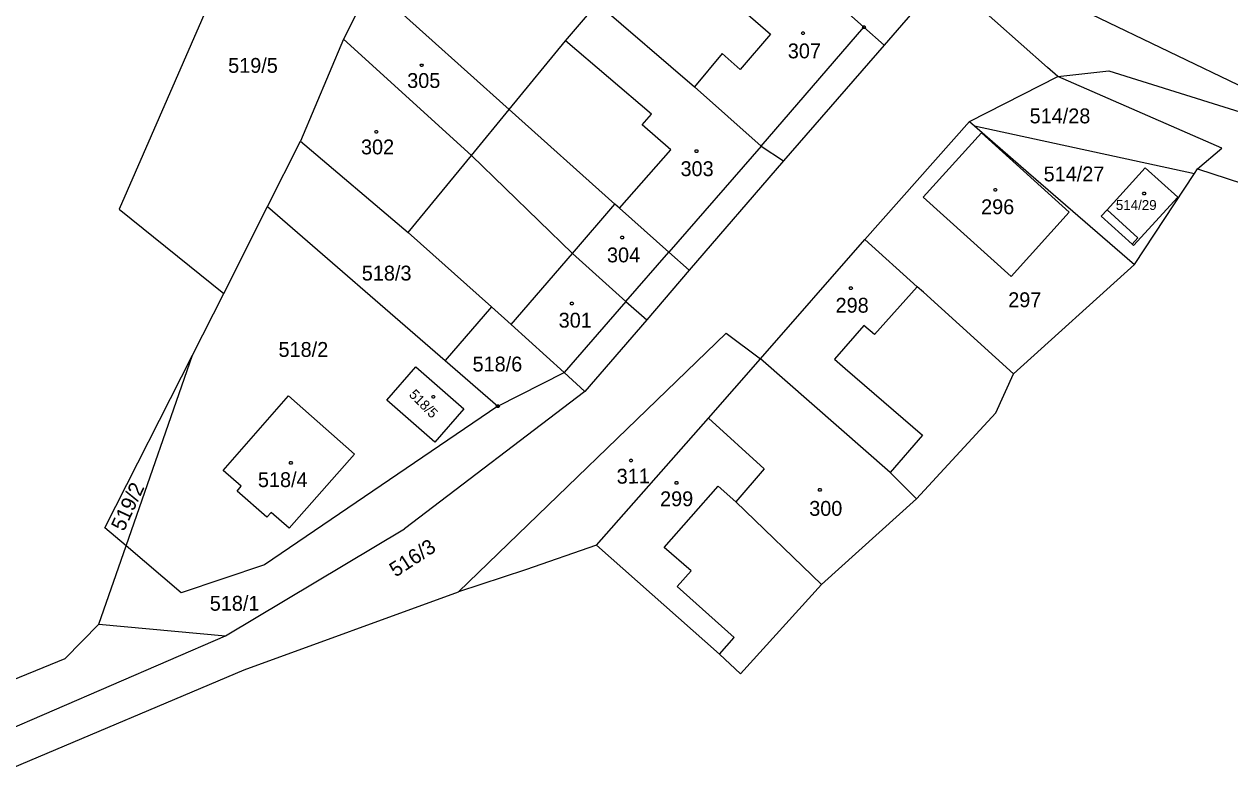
# Model space of a CAD drawing. Extents: x -634640 to -629202, y -1196156 to -1190068.
# Drawn here: x -631922.1 to -631784.1, y -1192813.3 to -1192727.8 of the extents above; entities that cross this region are included whole.
import ezdxf

# ---------------------------------------------------------------- set-up
doc = ezdxf.new("R2010")
doc.units = 0
for name, color, linetype in [('Vrstva 1', 7, 'Continuous'), ('Vrstva 2', 7, 'Continuous'), ('Vrstva 3', 7, 'Continuous'), ('Vrstva 4', 7, 'Continuous'), ('Vrstva 5', 7, 'Continuous'), ('Vrstva 8', 7, 'Continuous')]:
    doc.layers.add(name, color=color, linetype=linetype)

msp = doc.modelspace()

# ---------------------------------------------------------------- linework, layer by layer
at = {"layer": 'Vrstva 1'}
for p, q in [((-631845.21, -1192711.13), (-631825.94, -1192728.19)), ((-631816.78, -1192722.29), (-631823.63, -1192730.27)), ((-631882.43, -1192723.39), (-631885.53, -1192729.56)), ((-631882.43, -1192723.39), (-631866.57, -1192737.61)), ((-631860.1, -1192729.75), (-631856.45, -1192725.49)), ((-631856.45, -1192725.49), (-631845.36, -1192735.03)), ((-631804.93, -1192732.81), (-631814.33, -1192724.46)), ((-631782.1, -1192735.29), (-631799.89, -1192726.74)), ((-631825.94, -1192728.19), (-631823.63, -1192730.27)), ((-631885.53, -1192729.56), (-631890.46, -1192741.24)), ((-631885.53, -1192729.56), (-631870.89, -1192742.87)), ((-631866.57, -1192737.61), (-631860.1, -1192729.75)), ((-631823.63, -1192730.27), (-631835.15, -1192743.51)), ((-631813.87, -1192738.98), (-631803.76, -1192733.85)), ((-631803.76, -1192733.85), (-631804.93, -1192732.81)), ((-631803.76, -1192733.85), (-631797.91, -1192733.18)), ((-631784.98, -1192742.05), (-631803.76, -1192733.85)), ((-631797.91, -1192733.18), (-631759.33, -1192745.33)), ((-631845.36, -1192735.03), (-631837.71, -1192741.81)), ((-631870.89, -1192742.87), (-631866.57, -1192737.61)), ((-631854.45, -1192748.46), (-631866.57, -1192737.61)), ((-631825.83, -1192752.5), (-631813.87, -1192738.98)), ((-631813.87, -1192738.98), (-631813.29, -1192739.49)), ((-631813.29, -1192739.49), (-631807.11, -1192744.88)), ((-631813.29, -1192739.49), (-631788.11, -1192744.93)), ((-631819.15, -1192747.64), (-631812.48, -1192740.28)), ((-631812.48, -1192740.28), (-631802.46, -1192749.37)), ((-631894.22, -1192748.71), (-631890.46, -1192741.24)), ((-631890.46, -1192741.24), (-631878.11, -1192751.71)), ((-631837.71, -1192741.81), (-631835.15, -1192743.51)), ((-631787.77, -1192744.42), (-631784.98, -1192742.05)), ((-631878.11, -1192751.71), (-631870.89, -1192742.87)), ((-631870.89, -1192742.87), (-631859.32, -1192754.09)), ((-631835.15, -1192743.51), (-631845.94, -1192756.02)), ((-631807.11, -1192744.88), (-631794.96, -1192755.34)), ((-631794.96, -1192755.34), (-631788.11, -1192744.93)), ((-631788.11, -1192744.93), (-631787.77, -1192744.42)), ((-631787.77, -1192744.42), (-631778.3, -1192747.47)), ((-631809.1, -1192756.72), (-631819.15, -1192747.64)), ((-631899.23, -1192758.66), (-631894.22, -1192748.71)), ((-631894.22, -1192748.71), (-631873.88, -1192766.35)), ((-631853.91, -1192748.89), (-631854.45, -1192748.46)), ((-631848.27, -1192753.93), (-631853.91, -1192748.89)), ((-631802.46, -1192749.37), (-631809.1, -1192756.72)), ((-631878.11, -1192751.71), (-631868.6, -1192760.2)), ((-631837.78, -1192766.16), (-631825.83, -1192752.5)), ((-631819.85, -1192757.92), (-631825.83, -1192752.5)), ((-631859.32, -1192754.09), (-631853.2, -1192759.59)), ((-631845.94, -1192756.02), (-631848.27, -1192753.93)), ((-631845.94, -1192756.02), (-631850.81, -1192761.67)), ((-631808.82, -1192767.85), (-631794.96, -1192755.34)), ((-631902.8, -1192765.75), (-631899.23, -1192758.66)), ((-631819.13, -1192758.51), (-631819.85, -1192757.92)), ((-631808.82, -1192767.85), (-631819.13, -1192758.51)), ((-631868.6, -1192760.2), (-631873.88, -1192766.35)), ((-631868.6, -1192760.2), (-631866.34, -1192762.21)), ((-631853.2, -1192759.59), (-631850.81, -1192761.67)), ((-631850.81, -1192761.67), (-631857.9, -1192769.89)), ((-631866.34, -1192762.21), (-631860.28, -1192767.72)), ((-631872.35, -1192792.8), (-631841.7, -1192763.22)), ((-631841.7, -1192763.22), (-631837.78, -1192766.16)), ((-631912.85, -1192785.48), (-631902.8, -1192765.75)), ((-631910.42, -1192787.55), (-631902.8, -1192765.75)), ((-631873.88, -1192766.35), (-631867.85, -1192771.57)), ((-631843.74, -1192772.96), (-631837.78, -1192766.16)), ((-631822.95, -1192779.17), (-631837.78, -1192766.16)), ((-631867.85, -1192771.57), (-631860.28, -1192767.72)), ((-631860.28, -1192767.72), (-631857.9, -1192769.89)), ((-631810.86, -1192772.33), (-631808.82, -1192767.85)), ((-631857.9, -1192769.89), (-631878.54, -1192785.62)), ((-631867.85, -1192771.57), (-631894.58, -1192789.74)), ((-631819.94, -1192782.17), (-631810.86, -1192772.33)), ((-631856.56, -1192787.49), (-631843.74, -1192772.96)), ((-631843.74, -1192772.96), (-631837.35, -1192778.76)), ((-631837.35, -1192778.76), (-631840.63, -1192782.51)), ((-631819.94, -1192782.17), (-631822.95, -1192779.17)), ((-631819.94, -1192782.17), (-631830.81, -1192791.99)), ((-631840.63, -1192782.51), (-631830.81, -1192791.99)), ((-631910.42, -1192787.55), (-631912.85, -1192785.48)), ((-631899.04, -1192797.87), (-631878.54, -1192785.62)), ((-631913.55, -1192796.51), (-631910.42, -1192787.55)), ((-631904.09, -1192792.92), (-631910.42, -1192787.55)), ((-631856.56, -1192787.49), (-631864.7, -1192790.29)), ((-631842.5, -1192799.96), (-631856.56, -1192787.49)), ((-631894.58, -1192789.74), (-631904.09, -1192792.92)), ((-631864.7, -1192790.29), (-631872.35, -1192792.8)), ((-631830.81, -1192791.99), (-631840.07, -1192802.22)), ((-631896.9, -1192801.74), (-631872.35, -1192792.8)), ((-631917.39, -1192800.45), (-631913.55, -1192796.51)), ((-631913.55, -1192796.51), (-631899.04, -1192797.87)), ((-631925.18, -1192809.17), (-631899.04, -1192797.87)), ((-631840.07, -1192802.22), (-631842.5, -1192799.96)), ((-631956.23, -1192816.21), (-631917.39, -1192800.45)), ((-631923.43, -1192812.98), (-631896.9, -1192801.74))]:
    msp.add_line(p, q, dxfattribs=at)
for points in [[(-631893.53, -1192708.5), (-631911.2, -1192749.01), (-631899.23, -1192758.66)], [(-631790.03, -1192747.65), (-631793.74, -1192744.29), (-631798.11, -1192749.1)], [(-631795.26, -1192753.03), (-631795.07, -1192753.2), (-631790.03, -1192747.65)], [(-631798.11, -1192749.1), (-631798.79, -1192749.84), (-631795.26, -1192753.03)], [(-631880.58, -1192770.88), (-631877.25, -1192767.07), (-631871.73, -1192771.88), (-631875.07, -1192775.68), (-631880.58, -1192770.88)], [(-631891.74, -1192785.54), (-631893.82, -1192783.72), (-631894.31, -1192784.29), (-631897.71, -1192781.31), (-631897.22, -1192780.74), (-631899.3, -1192778.92), (-631891.81, -1192770.38), (-631884.26, -1192777.06), (-631891.74, -1192785.54)]]:
    msp.add_lwpolyline(points, dxfattribs=at)
at = {"layer": 'Vrstva 3'}
for points in [[(-631876.49, -1192732.41), (-631876.4, -1192732.56), (-631876.49, -1192732.71), (-631876.67, -1192732.71), (-631876.76, -1192732.56), (-631876.67, -1192732.41), (-631876.49, -1192732.41)], [(-631881.68, -1192740.03), (-631881.59, -1192740.18), (-631881.68, -1192740.33), (-631881.86, -1192740.33), (-631881.95, -1192740.18), (-631881.86, -1192740.03), (-631881.68, -1192740.03)], [(-631852.52, -1192777.63), (-631852.43, -1192777.78), (-631852.52, -1192777.93), (-631852.7, -1192777.93), (-631852.79, -1192777.78), (-631852.7, -1192777.63), (-631852.52, -1192777.63)], [(-631830.91, -1192780.99), (-631830.82, -1192781.14), (-631830.91, -1192781.29), (-631831.09, -1192781.29), (-631831.18, -1192781.14), (-631831.09, -1192780.99), (-631830.91, -1192780.99)]]:
    msp.add_lwpolyline(points, dxfattribs=at)
at = {"layer": 'Vrstva 4'}
for p, q in [((-631843.6, -1192722.93), (-631836.65, -1192729.01)), ((-631837.71, -1192741.81), (-631825.94, -1192728.19)), ((-631850.26, -1192738.14), (-631860.1, -1192729.75)), ((-631836.65, -1192729.01), (-631840.1, -1192733.04)), ((-631842.16, -1192731.21), (-631845.36, -1192735.03)), ((-631840.1, -1192733.04), (-631842.16, -1192731.21)), ((-631851.33, -1192739.37), (-631850.26, -1192738.14)), ((-631848.07, -1192742.22), (-631851.33, -1192739.37)), ((-631853.91, -1192748.89), (-631848.07, -1192742.22)), ((-631837.71, -1192741.81), (-631848.27, -1192753.93)), ((-631859.32, -1192754.09), (-631854.45, -1192748.46)), ((-631866.34, -1192762.21), (-631859.32, -1192754.09)), ((-631853.2, -1192759.59), (-631848.27, -1192753.93)), ((-631819.85, -1192757.92), (-631824.72, -1192763.35)), ((-631853.2, -1192759.59), (-631860.28, -1192767.72)), ((-631825.94, -1192762.33), (-631829.3, -1192766.18)), ((-631824.72, -1192763.35), (-631825.94, -1192762.33)), ((-631829.3, -1192766.18), (-631828.09, -1192767.24)), ((-631828.09, -1192767.24), (-631819.25, -1192774.89)), ((-631819.25, -1192774.89), (-631822.95, -1192779.17)), ((-631848.81, -1192787.73), (-631842.64, -1192780.73)), ((-631842.64, -1192780.73), (-631840.63, -1192782.51)), ((-631845.73, -1192790.43), (-631848.81, -1192787.73)), ((-631847.34, -1192792.2), (-631845.73, -1192790.43)), ((-631840.79, -1192798.04), (-631847.34, -1192792.2)), ((-631842.5, -1192799.96), (-631840.79, -1192798.04))]:
    msp.add_line(p, q, dxfattribs=at)
msp.add_lwpolyline([(-631798.11, -1192749.1), (-631794.58, -1192752.29), (-631795.26, -1192753.03)], dxfattribs=at)
at = {"layer": 'Vrstva 5'}
for points in [[(-631832.84, -1192728.73), (-631832.75, -1192728.88), (-631832.84, -1192729.03), (-631833.02, -1192729.03), (-631833.11, -1192728.88), (-631833.02, -1192728.73), (-631832.84, -1192728.73)], [(-631845.02, -1192742.25), (-631844.93, -1192742.4), (-631845.02, -1192742.55), (-631845.2, -1192742.55), (-631845.29, -1192742.4), (-631845.2, -1192742.25), (-631845.02, -1192742.25)], [(-631810.81, -1192746.67), (-631810.72, -1192746.82), (-631810.81, -1192746.97), (-631810.99, -1192746.97), (-631811.08, -1192746.82), (-631810.99, -1192746.67), (-631810.81, -1192746.67)], [(-631793.78, -1192747.09), (-631793.69, -1192747.24), (-631793.78, -1192747.39), (-631793.96, -1192747.39), (-631794.05, -1192747.24), (-631793.96, -1192747.09), (-631793.78, -1192747.09)], [(-631853.54, -1192752.13), (-631853.45, -1192752.28), (-631853.54, -1192752.43), (-631853.72, -1192752.43), (-631853.81, -1192752.28), (-631853.72, -1192752.13), (-631853.54, -1192752.13)], [(-631827.35, -1192757.93), (-631827.26, -1192758.08), (-631827.35, -1192758.23), (-631827.53, -1192758.23), (-631827.62, -1192758.08), (-631827.53, -1192757.93), (-631827.35, -1192757.93)], [(-631859.29, -1192759.68), (-631859.2, -1192759.83), (-631859.29, -1192759.98), (-631859.47, -1192759.98), (-631859.56, -1192759.83), (-631859.47, -1192759.68), (-631859.29, -1192759.68)], [(-631875.15, -1192770.35), (-631875.06, -1192770.5), (-631875.15, -1192770.65), (-631875.33, -1192770.65), (-631875.42, -1192770.5), (-631875.33, -1192770.35), (-631875.15, -1192770.35)], [(-631891.46, -1192777.92), (-631891.37, -1192778.07), (-631891.46, -1192778.22), (-631891.64, -1192778.22), (-631891.73, -1192778.07), (-631891.64, -1192777.92), (-631891.46, -1192777.92)], [(-631847.31, -1192780.18), (-631847.22, -1192780.33), (-631847.31, -1192780.48), (-631847.49, -1192780.48), (-631847.58, -1192780.33), (-631847.49, -1192780.18), (-631847.31, -1192780.18)]]:
    msp.add_lwpolyline(points, dxfattribs=at)
at = {"layer": 'Vrstva 8'}
for points in [[(-631825.85, -1192728.04), (-631825.76, -1192728.19), (-631825.85, -1192728.34), (-631826.03, -1192728.34), (-631826.12, -1192728.19), (-631826.03, -1192728.04), (-631825.85, -1192728.04)], [(-631867.76, -1192771.42), (-631867.67, -1192771.57), (-631867.76, -1192771.72), (-631867.94, -1192771.72), (-631868.03, -1192771.57), (-631867.94, -1192771.42), (-631867.76, -1192771.42)]]:
    msp.add_lwpolyline(points, dxfattribs=at)

# ---------------------------------------------------------------- texts
at = {"layer": 'Vrstva 2'}
for s, height, p in [('307', 1.7, (-631834.663, -1192731.76)), ('519/5', 1.7, (-631898.73, -1192733.42)), ('305', 1.7, (-631878.233, -1192735.15)), ('514/28', 1.7, (-631806.981, -1192739.2)), ('302', 1.7, (-631883.523, -1192742.75)), ('303', 1.7, (-631846.943, -1192745.24)), ('514/27', 1.7, (-631805.377, -1192745.84)), ('296', 1.7, (-631812.533, -1192749.6)), ('514/29', 1.14, (-631797.104, -1192749.12)), ('304', 1.7, (-631855.363, -1192755.11)), ('518/3', 1.7, (-631883.43, -1192757.19)), ('297', 1.7, (-631809.433, -1192760.24)), ('298', 1.7, (-631829.193, -1192760.87)), ('301', 1.7, (-631860.893, -1192762.58)), ('518/2', 1.7, (-631892.963, -1192765.93)), ('518/6', 1.7, (-631870.75, -1192767.6)), ('518/4', 1.7, (-631895.321, -1192780.83)), ('299', 1.7, (-631849.283, -1192783.02)), ('300', 1.7, (-631832.213, -1192784.12)), ('518/1', 1.7, (-631900.833, -1192794.98))]:
    msp.add_text(s, height=height, dxfattribs=at).set_placement(p)
for s, height, rotation, p in [('518/5', 1.14, 314.78301, (-631878.102, -1192770.335)), ('311', 1.7, 0.80214, (-631854.243, -1192780.447)), ('519/2', 1.7, 65.03071, (-631910.67, -1192785.985)), ('516/3', 1.7, 33.23155, (-631879.558, -1192791.198))]:
    msp.add_text(s, height=height, rotation=rotation, dxfattribs=at).set_placement(p)

doc.saveas('drawing.dxf')
